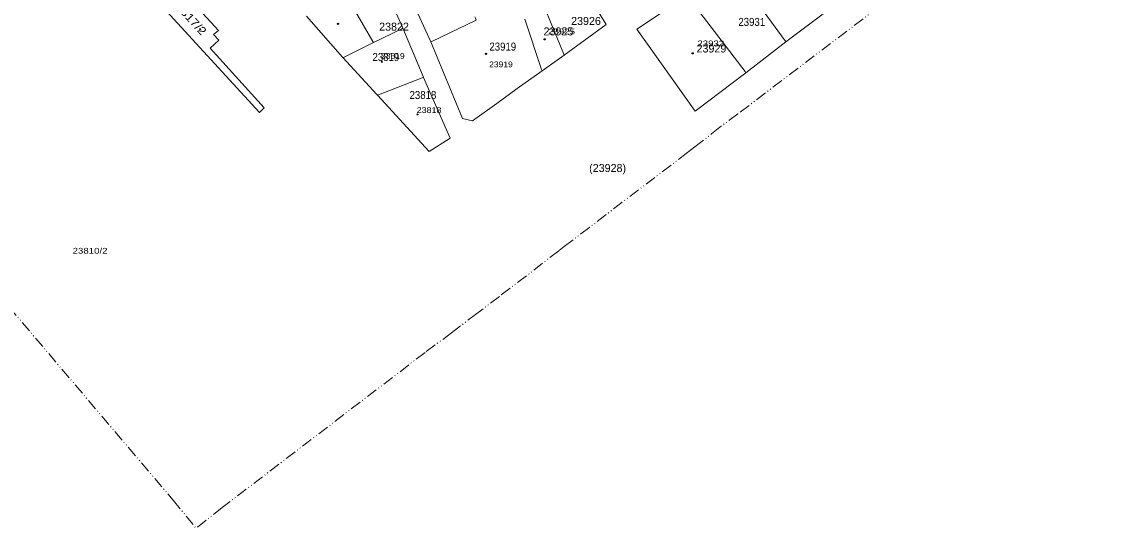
# Model space of a CAD drawing. Extents: x 649608 to 651081, y 237980 to 241202.
# Drawn here: x 650489.8 to 650982.5, y 237980 to 238207.6 of the extents above; entities that cross this region are included whole.
import ezdxf

# ---------------------------------------------------------------- set-up
doc = ezdxf.new("R2010")
doc.units = 0
doc.header["$PDMODE"] = 32
doc.header["$PDSIZE"] = 0.5
doc.linetypes.add('DASH_DOUBLE_DOT', pattern=[9.2, 5, -1.2, 0.3, -1.2, 0.3, -1.2])
for name, color, linetype in [('19', 7, 'Continuous'), ('20', 7, 'Continuous'), ('6', 7, 'Continuous')]:
    doc.layers.add(name, color=color, linetype=linetype)
for name, color, linetype, lineweight in [('3', 7, 'Continuous', 13), ('5', 7, 'Continuous', 13), ('52', 7, 'DASH_DOUBLE_DOT', 13)]:
    doc.layers.add(name, color=color, linetype=linetype, lineweight=lineweight)

msp = doc.modelspace()

# ---------------------------------------------------------------- linework, layer by layer
at = {"layer": '3'}
for points in [[(650598.74, 238168.998), (650574.582, 238195.781), (650578.476, 238199.463), (650576.052, 238201.939), (650578.203, 238203.679), (650543.51, 238241.706), (650541.23, 238239.462)], [(650833.498, 238198.629), (650852.011, 238212.621), (650841.55, 238231.355), (650833.028, 238244.372)], [(650733.752, 238192.67), (650752.648, 238206.409), (650742.2, 238223.611), (650731.986, 238240.663)], [(650649.081, 238231.778), (650661.143, 238204.909), (650661.217, 238204.732)], [(650659.214, 238231.401), (650662.994, 238222.68), (650663.128, 238222.38), (650668.008, 238211.416), (650673.734, 238198.611)], [(650538.247, 238230.705), (650571.563, 238194.27), (650596.69, 238166.88), (650598.74, 238168.998)], [(650789.131, 238219.424), (650766.398, 238204.401), (650792.759, 238167.518), (650815.522, 238184.763), (650833.498, 238198.629)], [(650634.266, 238191.546), (650634.118, 238191.708), (650617.856, 238210.25)], [(650661.217, 238204.732), (650670.277, 238182.988), (650670.435, 238182.63)], [(650673.734, 238198.611), (650688.059, 238164.189), (650692.479, 238163.074)], [(650692.479, 238163.074), (650703.489, 238170.964), (650712.604, 238177.696), (650723.792, 238185.662), (650733.752, 238192.67)], [(650649.752, 238174.63), (650649.475, 238174.931), (650634.266, 238191.546)], [(650670.435, 238182.63), (650682.493, 238155.359), (650673.021, 238149.386), (650649.752, 238174.63)]]:
    msp.add_lwpolyline(points, dxfattribs=at)
at = {"layer": '5'}
for points in [[(650634.341, 238221.901), (650634.631, 238221.401), (650647.745, 238198.783), (650648.035, 238198.283)], [(650815.522, 238184.763), (650815.141, 238185.263), (650789.512, 238218.924), (650789.131, 238219.424)], [(650833.498, 238198.629), (650833.135, 238199.129), (650817.634, 238220.462)], [(650725.102, 238213.833), (650733.548, 238193.17), (650733.752, 238192.67)], [(650673.734, 238198.611), (650674.234, 238198.851), (650694.13, 238208.411), (650693.818, 238209.325), (650693.647, 238209.825)], [(650716.041, 238208.793), (650723.624, 238186.162), (650723.792, 238185.662)], [(650661.217, 238204.732), (650660.717, 238204.487), (650648.035, 238198.283)], [(650648.035, 238198.283), (650634.766, 238191.791), (650634.266, 238191.546)], [(650649.752, 238174.63), (650650.252, 238174.823), (650669.935, 238182.437), (650670.435, 238182.63)]]:
    msp.add_lwpolyline(points, dxfattribs=at)
at = {"layer": '52'}
for points in [[(649701.481, 241202.319), (649640.936, 240904.262), (649608.393, 240352.424), (649614.771, 240009.578), (649631.5, 239894.49), (649662.347, 239679.564), (649715.192, 239448.546), (649776.71, 239295.263), (649918.979, 238940.568), (649995.713, 238777.318), (650020.382, 238724.355), (650126.69, 238550.145), (650295.37, 238327.169), (650466.153, 238100.489), (650557.889, 237992.529), (650568.158, 237979.989)], [(650971.563, 238303.584), (650982.492, 238295.992), (650978.586, 238293.02), (650970.875, 238286.874), (650811.903, 238166.241), (650803.737, 238160.273), (650800.084, 238157.225)], [(650683.109, 238067.856), (650693.301, 238075.577), (650705.487, 238084.805), (650731.574, 238104.817), (650733.818, 238106.56), (650741.305, 238112.329), (650788.623, 238148.376), (650792.505, 238151.401), (650800.084, 238157.225)], [(650683.109, 238067.856), (650671.201, 238058.934), (650579.925, 237989.223), (650568.158, 237979.989)]]:
    msp.add_lwpolyline(points, dxfattribs=at)
at = {"layer": '6'}
for p in [(650632.045, 238206.723), (650570.02, 238204.293), (650724.966, 238199.747), (650698.609, 238193.245), (650791.551, 238193.471), (650651.731, 238189.681), (650667.742, 238166.008)]:
    msp.add_point(p, dxfattribs=at)

# ---------------------------------------------------------------- texts
at = {"layer": '19', "width": 1.2}
msp.add_text('23817/2', height=3.6, rotation=312.44, dxfattribs=at).set_placement((650556.482, 238216.692))
at = {"layer": '19'}
for s, p in [('23822', (650650.526, 238203.666)), ('23926', (650736.883, 238206.226)), ('23925', (650724.486, 238201.533)), ('23929', (650793.314, 238193.854)), ('(23928)', (650745.005, 238140.101))]:
    msp.add_text(s, height=3.6, dxfattribs=at).set_placement(p)
at = {"layer": '19', "width": 0.9}
for s, p in [('23931', (650812.124, 238205.799)), ('23919', (650700.116, 238194.707)), ('23819', (650647.533, 238190.015)), ('23818', (650664.205, 238172.95))]:
    msp.add_text(s, height=3.6, dxfattribs=at).set_placement(p)
at = {"layer": '20'}
for s, width, p in [('23925', 1.25, (650726.541, 238202.001)), ('23932', 1.25, (650793.668, 238196.632)), ('23819', 1.1, (650651.381, 238190.981)), ('23919', 1.1, (650700.002, 238187.193)), ('23818', 1.15, (650667.434, 238166.657)), ('23810/2', 1.25, (650512.641, 238103.386))]:
    msp.add_text(s, height=2.6, dxfattribs=dict(at, width=width)).set_placement(p)

doc.saveas('drawing.dxf')
